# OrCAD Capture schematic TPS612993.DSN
size A
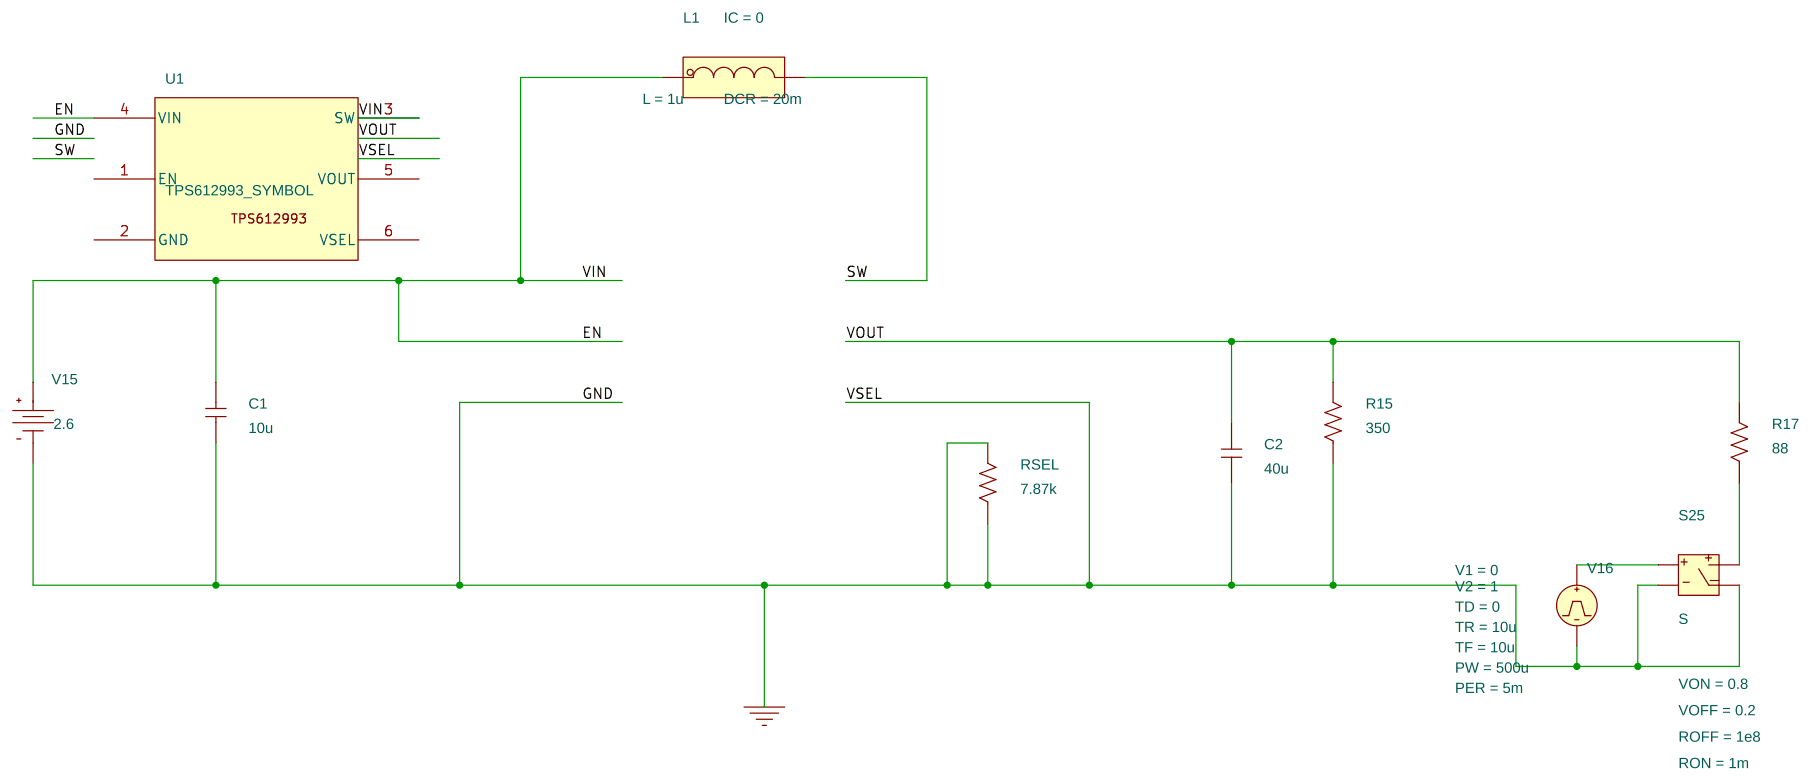
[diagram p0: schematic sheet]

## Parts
C1  10u  [RAD/CK05]
C2  40u  [RAD/CK05]
L1  LDCR
R15  350  [AX/RC05]
R17  88  [AX/RC05]
RSEL  7.87k  [AX/RC05]
S25  S
U1  TPS612993_SYMBOL
V15  VDC
V16  VPULSE

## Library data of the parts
C1 C2 = C
L1 = LDCR: DCR: 20m; IC: 0; L: 1u; PSpiceTemplate: X^@REFDES %IN %OUT @MODEL PARAMS:  ?L|L=@L||L=1u|  ?DCR|DCR=@DCR||DCR=0.01| ?IC|IC=@IC||IC=0|
R15 R17 RSEL = R
S25 = S: ROFF: 1e8; RON: 1m; VOFF: 0.2; VON: 0.8
U1 = TPS612993_SYMBOL_1
V15 = VDC: DC: 2.6
V16 = VPULSE: PER: 5m; PW: 500u; TD: 0; TF: 10u; TR: 10u; V1: 0; V2: 1

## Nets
0: C1.2 C2.2 R15.1 RSEL.1 RSEL.2 S25.1(2) S25.3(4) V15.1(-) V16.2(-)
EN: C1.1 L1.1(IN) U1.3(SW) U1.4(VIN) V15.0(+)
SW: L1.3(OUT)
VOUT: C2.1 R15.2 R17.2
N16775787: R17.1 S25.2(3)
N16775839: S25.0(1) V16.1(+)

Not connected (* = marked no-connect by the designer): U1 1(EN) 2(GND) 5(VOUT) 6(VSEL)
